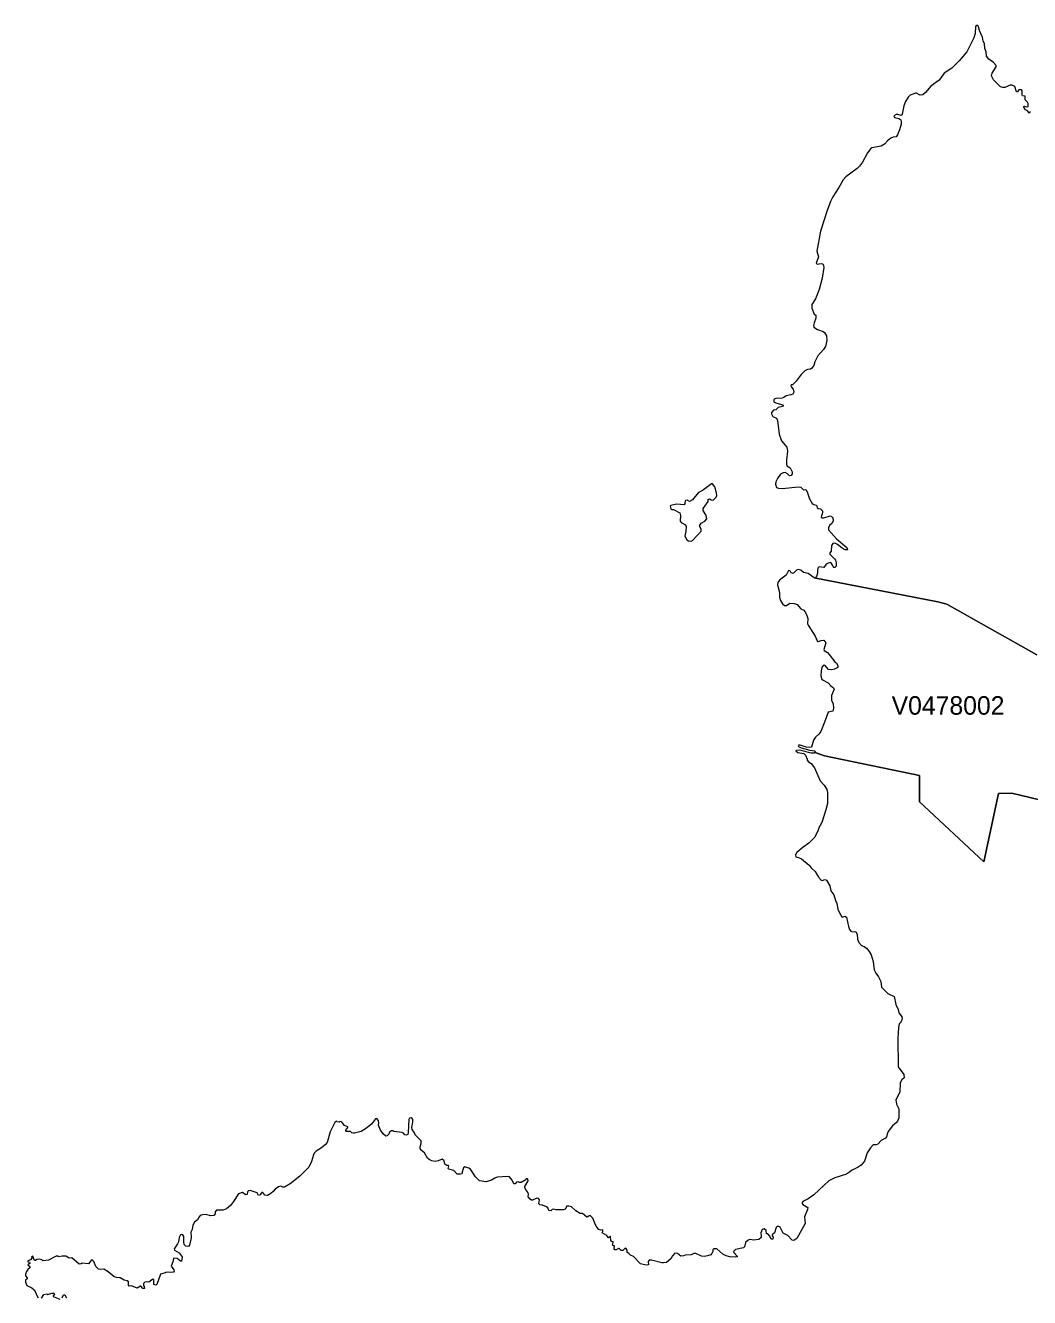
# Model space of a CAD drawing. Extents: x 369010 to 735936, y 6377141 to 6616555.
# Drawn here: x 445777 to 451203, y 6497979 to 6504854 of the extents above; entities that cross this region are included whole.
import ezdxf
from ezdxf.enums import TextEntityAlignment as Align

# ---------------------------------------------------------------- set-up
doc = ezdxf.new("R2010")
doc.units = 0
doc.header["$LTSCALE"] = 40
doc.layers.add('3', color=7, linetype='Continuous', lineweight=13)
doc.layers.add('4', color=7, linetype='Continuous')

msp = doc.modelspace()

# ---------------------------------------------------------------- linework, layer by layer
at = {"layer": '3'}
for points in [[(451162.75, 6504500.78), (451159.61, 6504506.24), (451152.82, 6504508.06), (451144.21, 6504505.58), (451137.92, 6504495.65), (451132.46, 6504496.31), (451123.69, 6504524.45), (451108.8, 6504531.24), (451097.87, 6504532.06), (451069.57, 6504519.48), (451058.65, 6504518.82), (451045.74, 6504521.97), (451007.84, 6504560.53), (450997.41, 6504581.38), (451001.22, 6504596.11), (451022.9, 6504630.7), (451022.24, 6504637.16), (451007.51, 6504655.03), (450982.02, 6504672.91), (450970.1, 6504688.96), (450967.95, 6504711.3), (450960.83, 6504730.5), (450959.51, 6504756.82), (450952.23, 6504769.56), (450948.09, 6504791.74), (450944.45, 6504798.03), (450931.54, 6504827.82), (450926.91, 6504846.52), (450922.44, 6504854.46), (450918.63, 6504854.46), (450909.86, 6504848.01), (450908.7, 6504810.61), (450902.08, 6504786.77), (450863.19, 6504712.63), (450823.14, 6504662.48), (450782.26, 6504624.25), (450741.87, 6504596.77), (450714.73, 6504559.37), (450668.89, 6504525.44), (450640.09, 6504492.18), (450625.69, 6504479.6), (450611.62, 6504477.78), (450592.09, 6504489.2), (450586.3, 6504489.2), (450557.5, 6504477.78), (450546.58, 6504466.85), (450531.52, 6504443.85), (450523.24, 6504420.68), (450513.97, 6504375.33), (450509.17, 6504366.89), (450491.63, 6504373.01), (450482.69, 6504372.35), (450469.78, 6504366.06), (450473.59, 6504357.29), (450496.1, 6504351.66), (450507.52, 6504344.55), (450509.51, 6504334.29), (450508.18, 6504320.22), (450499.91, 6504289.76), (450489.64, 6504263.95), (450482.69, 6504253.35), (450465.32, 6504251.04), (450452.57, 6504244.75), (450435.86, 6504231.18), (450419.8, 6504213.63), (450400.6, 6504201.55), (450350.46, 6504192.12), (450344.99, 6504189.3), (450326.46, 6504165.97), (450300.47, 6504115.99), (450284.09, 6504093.64), (450271.35, 6504081.4), (450209.61, 6504036.05), (450195.21, 6504019.99), (450172.7, 6503978.29), (450139.77, 6503928.47), (450126.69, 6503903.48), (450108.49, 6503853.5), (450073.24, 6503742.11), (450054.04, 6503633.87), (450061.65, 6503603.25), (450049.57, 6503568.99), (450055.86, 6503564.03), (450076.71, 6503568), (450085.32, 6503565.19), (450090.12, 6503557.74), (450091.11, 6503546.32), (450081.18, 6503488.06), (450066.45, 6503426.5), (450045.76, 6503376.68), (450026.56, 6503345.9), (450026.73, 6503326.7), (450038.48, 6503293.43), (450047.09, 6503287.97), (450048.41, 6503272.91), (450038.48, 6503247.75), (450035.17, 6503232.69), (450037.82, 6503224.58), (450057.02, 6503211.18), (450087.64, 6503200.58)], [(451204.79, 6504388.74), (451202.14, 6504380.96), (451189.06, 6504394.2), (451181.12, 6504398.34), (451172.02, 6504412.73), (451172.02, 6504416.87), (451176.32, 6504417.53), (451185.59, 6504414.06), (451194.86, 6504417.2), (451195.85, 6504432.93), (451192.21, 6504439.88), (451179.8, 6504451.79), (451178.8, 6504471.98), (451164.74, 6504473.81), (451162.42, 6504477.45), (451162.75, 6504500.78)], [(450087.64, 6503200.58), (450095.25, 6503194.13), (450105.84, 6503177.74), (450107.83, 6503152.59), (450099.55, 6503118.82), (450089.46, 6503103.1), (450058.01, 6503069.67), (450041.96, 6503036.24), (450036.49, 6503017.37), (450026.56, 6503001.98), (450019.45, 6502997.68), (450002.73, 6502994.2), (449988, 6502987.41), (449969.3, 6502968.22), (449942.32, 6502931.14), (449921.14, 6502911.94), (449914.35, 6502912.61), (449912.2, 6502908.3), (449913.69, 6502902.18), (449924.61, 6502888.11), (449929.74, 6502872.06), (449924.28, 6502862.46), (449912.7, 6502857.99), (449887.71, 6502852.69), (449874.14, 6502843.09), (449865.86, 6502840.61), (449832.43, 6502838.29), (449822.83, 6502834.16), (449820.18, 6502829.03), (449820.18, 6502822.9), (449822.83, 6502819.26), (449836.24, 6502812.97), (449868.67, 6502803.54), (449871.65, 6502800.06), (449867.52, 6502794.93), (449844.68, 6502789.47), (449832.43, 6502777.89), (449818.2, 6502774.74), (449808.6, 6502762.49), (449808.93, 6502755.38), (449815.05, 6502741.81), (449834.41, 6502731.54), (449839.88, 6502719.96), (449850.14, 6502644.82), (449862.55, 6502609.4), (449891.51, 6502574.48), (449894.16, 6502554.12), (449888.7, 6502507.29), (449888.7, 6502482.79), (449891.84, 6502475.18), (449908.89, 6502463.59), (449920.48, 6502441.42), (449920.48, 6502430.82), (449913.69, 6502421.72), (449908.23, 6502419.57), (449903.1, 6502421.39), (449895.49, 6502431.15), (449881.91, 6502438.11), (449870.99, 6502435.95), (449856.26, 6502429.17), (449839.88, 6502406.66), (449832.1, 6502388.29), (449830.77, 6502375.55), (449835.9, 6502358.17), (449845.34, 6502353.7), (449868.34, 6502351.38), (449953.25, 6502361.31), (449966.82, 6502359.16), (449980.89, 6502344.6), (449994.13, 6502345.92), (450000.91, 6502334.34), (450013.66, 6502295.77), (450028.22, 6502270.45), (450037.49, 6502265.32), (450051.89, 6502261.02), (450055.86, 6502247.61), (450060, 6502243.64), (450073.4, 6502242.81), (450083.83, 6502231.89), (450084.33, 6502219.97), (450077.71, 6502204.75), (450077.04, 6502196.47), (450081.18, 6502192.66), (450091.44, 6502192.66), (450124.87, 6502203.26), (450137.45, 6502196.47), (450142.25, 6502183.56), (450142.25, 6502175.95), (450135.14, 6502163.04), (450122.06, 6502152.45), (450115.94, 6502139.54), (450117.1, 6502127.62), (450159.63, 6502079.46), (450215.57, 6502032.95), (450219.38, 6502022.86), (450217.06, 6502020.37), (450207.13, 6502020.04), (450190.08, 6502029.97), (450165.42, 6502049.5), (450150.86, 6502055.63)], [(450150.86, 6502055.63), (450139.93, 6502054.14), (450132.65, 6502043.88), (450130.67, 6502012.93), (450123.22, 6502004.98), (450123.22, 6501996.54), (450148.71, 6501972.38), (450153.84, 6501964.76), (450158.31, 6501949.37), (450157.64, 6501932.33), (450151.19, 6501924.88), (450144.9, 6501925.21), (450140.93, 6501928.35), (450136.46, 6501941.26), (450128.35, 6501951.52), (450113.95, 6501949.04), (450103.36, 6501943.25), (450091.44, 6501924.55), (450066.45, 6501927.69), (450058.34, 6501921.07), (450056.19, 6501909.49), (450056.36, 6501893.43), (450052.22, 6501876.72), (450044.94, 6501867.94), (450038.81, 6501868.61)], [(451242.85, 6501453.52), (450756.27, 6501726.94), (450707.28, 6501740.01), (450038.98, 6501868.61), (450038.81, 6501868.61), (450038.81, 6501868.61), (450007.2, 6501892.77), (449981.55, 6501898.23), (449966.16, 6501909.82), (449951.92, 6501913.95), (449943.32, 6501911.31), (449925.28, 6501893.1), (449914.35, 6501896.58), (449911.54, 6501904.02), (449906.91, 6501907.5), (449900.95, 6501907.83), (449888.04, 6501883.67), (449851.13, 6501856.03), (449841.7, 6501843.95), (449840.21, 6501831.04), (449851.46, 6501789.33), (449851.46, 6501764.17), (449856.76, 6501747.46), (449867.85, 6501728.26), (449878.77, 6501718.83), (449889.69, 6501718.83), (449908.23, 6501733.06), (449931.4, 6501729.75), (449946.46, 6501724.62), (449967.15, 6501700.79), (449982.54, 6501693.83), (449989, 6501687.71), (449997.93, 6501671), (450003.73, 6501649.48), (450003.06, 6501620.85), (450006.21, 6501612.41), (450045.1, 6501554.65), (450055.53, 6501528.66), (450061.32, 6501525.35), (450076.71, 6501530.48), (450090.78, 6501531.81), (450102.37, 6501517.74), (450091.77, 6501481.99), (450093.76, 6501475.53), (450111.63, 6501464.94), (450120.74, 6501455.01), (450150.03, 6501414.79), (450158.97, 6501407.68), (450167.24, 6501394.93), (450166.75, 6501384.67), (450148.71, 6501375.24), (450131.99, 6501371.43), (450116.6, 6501373.75), (450096.9, 6501396.26), (450086.97, 6501395.27), (450080.85, 6501383.68), (450076.38, 6501366.96), (450075.39, 6501341.81), (450078.86, 6501323.93), (450087.3, 6501316.82), (450114.94, 6501300.76), (450128.68, 6501285.7), (450143.91, 6501274.12), (450147.38, 6501267.33), (450131.99, 6501233.9), (450131.66, 6501205.93), (450142.25, 6501189.54), (450143.91, 6501164.39), (450139.27, 6501149.33), (450113.95, 6501142.21), (450095.25, 6501089.25), (450074.4, 6501039.1), (450064.47, 6501023.71), (450046.76, 6501007.32), (450035.17, 6500991.6), (450028.72, 6500965.78), (450023.92, 6500954.53)], [(450038.81, 6501868.61), (450707.28, 6501740.01), (450756.27, 6501726.94), (451242.85, 6501453.52)], [(451301.77, 6500658.28), (451106.15, 6500705.44), (451034.65, 6500702.8), (450956.04, 6500334.05), (450608.64, 6500658.11), (450608.48, 6500800.78), (450094.59, 6500907.36), (450044.27, 6500925.07), (450039.47, 6500921.76), (450022.76, 6500921.76), (449959.37, 6500938.14), (449941.66, 6500936.32), (449939.51, 6500934.34), (449950.76, 6500924.41), (449982.21, 6500920.1), (449991.48, 6500909.84), (450000.25, 6500889.65), (450000.25, 6500882.87), (450007.53, 6500874.92), (450022.43, 6500865.16), (450040.96, 6500842.48), (450070.92, 6500771.32), (450092.44, 6500749.14), (450108.16, 6500724.81), (450111.14, 6500708.09), (450110.14, 6500649.5), (450102.7, 6500616.07), (450079.86, 6500546.73), (450061.65, 6500513.96), (450060, 6500506.18), (450041.63, 6500467.62), (450010.51, 6500435.84), (449979.23, 6500413.33), (449945.8, 6500385.36), (449938.19, 6500372.78), (449940.34, 6500360.7), (449954.57, 6500357.39), (449971.29, 6500349.78), (450011.83, 6500315.68), (450022.76, 6500301.12), (450043.61, 6500281.59), (450062.15, 6500250.97), (450076.05, 6500234.59), (450081.18, 6500233.43), (450096.9, 6500237.9), (450106.01, 6500234.59), (450123.55, 6500204.46), (450129.01, 6500178.31), (450145.4, 6500155.31), (450154.5, 6500124.36), (450161.28, 6500108.97), (450166.91, 6500078.18), (450173.04, 6500062.63), (450187.93, 6500036.64), (450192.73, 6500035.32), (450203.98, 6500040.12), (450213.92, 6500034.99), (450224.84, 6499984.84), (450230.47, 6499967.79), (450236.59, 6499960.35), (450246.19, 6499955.88), (450259.26, 6499958.53), (450264.06, 6499955.71), (450271.51, 6499943.13), (450273, 6499916.16), (450279.45, 6499898.12), (450294.02, 6499881.73), (450309.08, 6499876.6), (450321.66, 6499867.33), (450335.73, 6499849.95), (450345.99, 6499831.91), (450357.9, 6499796), (450363.37, 6499750.98), (450371.48, 6499731.95), (450385.87, 6499713.58), (450398.78, 6499686.6), (450401.93, 6499657.47), (450436.35, 6499622.06), (450471.6, 6499606.66), (450480.71, 6499563.8), (450492.29, 6499536.82), (450495.77, 6499518.95), (450515.13, 6499495.11), (450513.15, 6499494.45)], [(450023.92, 6500954.53), (450016.3, 6500952.05), (449996.28, 6500953.87), (449962.85, 6500965.45), (449953.91, 6500964.46), (449952.25, 6500960.65), (449953.91, 6500957.51), (449968.64, 6500950.72), (450014.98, 6500936.82), (450040.96, 6500933.34), (450043.94, 6500930.2), (450044.27, 6500925.07)], [(450044.27, 6500925.07), (450094.59, 6500907.36), (450608.48, 6500800.78), (450608.64, 6500658.11), (450956.04, 6500334.05), (451034.65, 6500702.8), (451106.15, 6500705.44), (451301.77, 6500658.28)], [(450513.15, 6499494.45), (450514.14, 6499488.66), (450510.83, 6499474.92), (450504.21, 6499462.34), (450498.75, 6499457.88), (450494.78, 6499438.51), (450491.63, 6499381.25), (450493.29, 6499227), (450522.75, 6499184.63), (450524.73, 6499166.59), (450511.82, 6499155.67), (450503.22, 6499140.6), (450502.55, 6499090.13), (450481.04, 6499048.09), (450483.85, 6499025.25), (450495.77, 6498999.43), (450495.77, 6498950.61), (450489.31, 6498932.4), (450483.85, 6498924.62), (450463, 6498906.91), (450438.17, 6498876.79), (450434.37, 6498867.69), (450430.23, 6498847.17), (450425.1, 6498840.71), (450400.93, 6498828.79), (450382.73, 6498808.27), (450373.63, 6498805.13), (450358.23, 6498804.47), (450342.51, 6498789.24), (450325.13, 6498762.26), (450310.9, 6498715.76), (450293.03, 6498694.24), (450277.47, 6498683.81), (450244.37, 6498667.43), (450212.92, 6498646.91), (450150.03, 6498626.05), (450117.76, 6498609.34), (450037.49, 6498534.36), (450006.87, 6498512.52), (449977.74, 6498497.79), (449974.43, 6498492.66), (449974.43, 6498488.52), (449978.07, 6498483.06), (450004.72, 6498466.67), (450002.73, 6498454.42), (449986.68, 6498415.53), (449989.66, 6498380.44), (449944.31, 6498297.86), (449928.26, 6498287.6), (449920.48, 6498289.91), (449895.98, 6498314.91), (449871.65, 6498327.81), (449854.61, 6498360.58), (449848.48, 6498363.73), (449838.55, 6498363.73), (449833.09, 6498358.6), (449824.65, 6498328.81), (449812.73, 6498317.55), (449812.73, 6498313.58), (449817.37, 6498305.31), (449815.05, 6498295.04), (449806.78, 6498295.04), (449798.67, 6498310.44), (449788.74, 6498323.35), (449781.29, 6498324.17), (449779.3, 6498342.21), (449768.05, 6498349.99), (449757.46, 6498346.35), (449750.84, 6498328.48), (449753.32, 6498310.44), (449751.66, 6498303.98), (449739.58, 6498293.39), (449711.61, 6498288.92), (449691.25, 6498293.06), (449682.32, 6498289.58), (449668.58, 6498276.34), (449662.79, 6498254.17), (449657.49, 6498248.7), (449614.13, 6498239.44), (449603.54, 6498228.51), (449603.87, 6498223.71), (449623.23, 6498203.36), (449622.57, 6498199.55), (449611.32, 6498196.9), (449582.35, 6498198.89), (449563.15, 6498204.68), (449544.45, 6498213.95), (449513.34, 6498241.92), (449498.44, 6498243.24), (449490.83, 6498236.79), (449491.16, 6498228.18), (449486.53, 6498216.6), (449480.24, 6498211.13), (449462.86, 6498204.35), (449444.16, 6498201.53), (449429.1, 6498202.36), (449399.8, 6498217.59), (449388.55, 6498216.93), (449374.81, 6498209.81), (449342.04, 6498209.15)], [(448392.21, 6498631.35), (448382.78, 6498634), (448326.01, 6498630.02), (448312.44, 6498625.23), (448294.9, 6498614.63), (448265.93, 6498605.53), (448230.02, 6498610.66), (448209, 6498632.01), (448181.86, 6498672.39), (448172.09, 6498678.85), (448150.91, 6498685.97), (448143.13, 6498680.5), (448135.35, 6498652.04), (448136.01, 6498648.89), (448127.9, 6498645.91), (448108.87, 6498646.24), (448091.99, 6498666.6), (448063.85, 6498673.72), (448061.37, 6498676.86), (448064.85, 6498690.76), (448061.7, 6498693.08), (448053.26, 6498693.08), (448043, 6498700.53), (448039.36, 6498717.58), (448029.1, 6498727.67), (448006.09, 6498717.58), (447992.52, 6498714.43), (447973.16, 6498718.9), (447958.59, 6498725.02), (447948.66, 6498733.13), (447933.77, 6498761.27), (447917.22, 6498774.51), (447909.11, 6498784.27), (447909.11, 6498793.54), (447915.56, 6498811.09), (447914.9, 6498825.48), (447883.29, 6498858.59), (447878.82, 6498870.17), (447866.24, 6498887.88), (447864.92, 6498898.97), (447869.72, 6498927.27), (447869.72, 6498941.83), (447866.57, 6498946.8), (447860.45, 6498950.61), (447852.34, 6498948.29), (447848.37, 6498942.17), (447844.89, 6498871.16), (447842.24, 6498861.4), (447833.31, 6498857.59), (447826.52, 6498858.59), (447819.4, 6498867.52), (447812.95, 6498871.5), (447767.6, 6498877.29), (447761.48, 6498881.09), (447755.35, 6498881.09), (447743.44, 6498872.65), (447740.46, 6498862.06), (447732.02, 6498852.96), (447724.74, 6498852.13), (447709.51, 6498863.72), (447694.94, 6498884.74), (447684.35, 6498910.55), (447685.51, 6498923.46), (447684.02, 6498934.39), (447678.06, 6498945.48), (447671.61, 6498946.47), (447667.8, 6498944.48), (447646.45, 6498917.01), (447614.51, 6498891.52), (447591.17, 6498876.63), (447555.59, 6498867.19), (447547.98, 6498867.19), (447539.87, 6498870.17), (447532.75, 6498876.63), (447509.41, 6498875.96), (447507.26, 6498879.44), (447507.92, 6498884.4), (447518.85, 6498897.98), (447518.52, 6498902.44), (447500.48, 6498908.9), (447488.73, 6498925.45), (447482.6, 6498930.58), (447473.33, 6498929.59), (447471.68, 6498927.27), (447460.09, 6498929.92), (447457.45, 6498932.23), (447449.01, 6498925.45), (447423.19, 6498875.63), (447406.47, 6498818.04), (447397.37, 6498807.44), (447376.35, 6498789.41), (447347.55, 6498770.04), (447337.62, 6498759.28), (447333.32, 6498751.5), (447321.73, 6498714.1), (447308.16, 6498683.32), (447259.67, 6498634.66), (447206.71, 6498593.61), (447177.25, 6498575.74), (447167.98, 6498575.74)], [(449342.04, 6498209.15), (449332.28, 6498205.01), (449318.54, 6498202.69), (449299.51, 6498218.25), (449286.43, 6498218.42), (449273.19, 6498205.67), (449264.42, 6498188.29), (449240.09, 6498168.93), (449224.37, 6498166.45), (449215.26, 6498167.11), (449160.65, 6498181.51), (449147.9, 6498181.51), (449141.78, 6498175.05), (449143.93, 6498156.52), (449130.53, 6498154.86), (449100.57, 6498160.99), (449062.01, 6498202.03), (449046.95, 6498208.82), (449036.85, 6498216.76), (449027.75, 6498222.06), (449027.42, 6498234.97), (449022.62, 6498244.23), (449017.16, 6498245.89), (449004.91, 6498233.31), (448995.47, 6498234.3), (448984.22, 6498244.9), (448981.24, 6498244.9), (448968.66, 6498236.79), (448960.88, 6498237.45), (448957.91, 6498243.24), (448960.22, 6498258.14), (448954.76, 6498258.47), (448948.97, 6498261.78), (448953.11, 6498276.34), (448951.78, 6498281.8), (448943.84, 6498279.82), (448941.19, 6498284.62), (448942.84, 6498286.6), (448940.86, 6498287.27), (448937.55, 6498308.62), (448935.07, 6498309.28), (448927.29, 6498302.49), (448924.97, 6498303.15), (448917.52, 6498314.74), (448893.36, 6498328.97), (448896.67, 6498336.75), (448896.01, 6498343.21), (448892.37, 6498344.7), (448884.26, 6498342.88), (448875.32, 6498346.68), (448864.89, 6498358.93), (448856.78, 6498372.83), (448843.54, 6498407.75), (448827.82, 6498423.64), (448822.19, 6498421.32), (448815.74, 6498414.87), (448810.61, 6498414.54), (448786.11, 6498432.91), (448774.2, 6498433.57), (448750.53, 6498447.47), (448727.85, 6498469.15), (448713.79, 6498472.46), (448702.37, 6498472.46), (448692.44, 6498457.57), (448685.98, 6498453.93), (448643.28, 6498453.27), (448629.05, 6498456.58), (448623.59, 6498454.59), (448616.47, 6498448.14), (448604.89, 6498450.45), (448599.26, 6498463.69), (448592.14, 6498469.49), (448570.96, 6498478.92), (448556.06, 6498479.75), (448551.26, 6498485.37), (448554.08, 6498508.21), (448549.61, 6498515), (448539.84, 6498515.66), (448517, 6498506.56), (448511.38, 6498506.56), (448504.26, 6498511.85), (448494, 6498524.1), (448495.98, 6498537.67), (448493.34, 6498545.12), (448483.07, 6498559.02), (448475.96, 6498572.93), (448474.96, 6498579.71), (448492.67, 6498610), (448491.68, 6498619.1), (448489.86, 6498621.09), (448483.07, 6498620.76), (448477.12, 6498613.97), (448455.6, 6498600.73), (448447.16, 6498601.06), (448438.39, 6498605.53), (448430.28, 6498602.22), (448422.5, 6498593.28), (448415.88, 6498593.94), (448407.11, 6498613.64), (448392.21, 6498631.35)], [(447167.98, 6498575.74), (447156.23, 6498580.7), (447144.64, 6498578.06), (447126.6, 6498564.82), (447115.35, 6498552.24), (447101.94, 6498541.48), (447083.9, 6498531.22), (447070.99, 6498532.54), (447059.08, 6498547.11), (447054.77, 6498547.27), (447049.98, 6498543.47), (447045.18, 6498534.36), (447036.4, 6498530.23), (447028.29, 6498544.46), (446990.23, 6498557.37), (446981.79, 6498556.04), (446976, 6498551.58), (446975.66, 6498536.68), (446967.89, 6498535.03), (446946.87, 6498547.93), (446927.34, 6498539.99), (446901.68, 6498498.28), (446884.64, 6498477.26), (446862.96, 6498458.56), (446845.41, 6498451.45), (446809.33, 6498451.45), (446801.55, 6498442.67), (446801.88, 6498431.75), (446795.1, 6498423.64), (446776.89, 6498420.99), (446753.06, 6498429.1), (446733.7, 6498426.79), (446720.46, 6498422.32), (446714.66, 6498415.53), (446706.89, 6498399.31), (446690.67, 6498386.4), (446681.07, 6498371.01), (446677.76, 6498346.35), (446670.64, 6498332.12), (446671.63, 6498303.15), (446669.32, 6498285.61), (446662.53, 6498261.78), (446657.07, 6498255.65), (446643.83, 6498256.48), (446634.73, 6498266.91), (446632.57, 6498279.82), (446632.24, 6498308.95), (446627.94, 6498317.88), (446620, 6498320.2), (446614.7, 6498318.88), (446607.09, 6498303.65), (446603.11, 6498280.48), (446598.98, 6498268.89), (446580.27, 6498242.41), (446582.43, 6498234.64), (446606.42, 6498221.06), (446623.47, 6498199.38), (446619.33, 6498176.38), (446614.7, 6498176.05), (446597.32, 6498189.95), (446578.29, 6498192.93), (446576.3, 6498190.94), (446573.65, 6498172.57), (446564.39, 6498149.24), (446578.95, 6498128.55), (446579.61, 6498121.43), (446577.3, 6498117.29), (446563.06, 6498114.31), (446539.89, 6498116.96), (446526.32, 6498110.84), (446505.63, 6498105.71), (446487.1, 6498050.43), (446480.31, 6498046.79), (446470.38, 6498050.1), (446469.72, 6498075.59), (446464.92, 6498077.9), (446442.91, 6498063.34), (446429.67, 6498064.66), (446421.56, 6498061.68), (446413.78, 6498055.23), (446415.43, 6498044.64), (446418.58, 6498038.84), (446419.57, 6498029.08), (446410.8, 6498027.76), (446400.87, 6498041), (446397.56, 6498041), (446380.51, 6498029.41), (446349.89, 6498042.32), (446336.82, 6498041.33), (446333.34, 6498046.46), (446333.34, 6498064.99), (446326.89, 6498069.13), (446309.68, 6498072.94), (446288.49, 6498086.34), (446268.47, 6498087.5), (446255.39, 6498092.14), (446223.12, 6498118.62), (446199.95, 6498132.19), (446183.07, 6498130.53), (446170.82, 6498132.85)], [(446170.82, 6498132.85), (446157.25, 6498147.91), (446146.65, 6498173.56), (446136.89, 6498182.83), (446131.1, 6498181.51), (446125.3, 6498169.92), (446117.86, 6498161.48), (446082.94, 6498164.46), (446077.8, 6498161.48), (446067.38, 6498160.66), (446027.66, 6498193.26), (446012.76, 6498192.93), (445994.06, 6498202.53), (445975.69, 6498203.19), (445955, 6498199.71), (445953.68, 6498202.86), (445942.09, 6498202.2), (445900.72, 6498181.34), (445870.92, 6498177.37), (445864.47, 6498182.5), (445850.9, 6498187.47), (445837.66, 6498185.81), (445830.05, 6498179.36), (445825.41, 6498179.85), (445815.98, 6498202.86), (445809.85, 6498199.71), (445810.52, 6498192.27), (445804.06, 6498183.83), (445788.83, 6498177.7), (445788.83, 6498173.23), (445797.61, 6498170.59), (445800.25, 6498167.44), (445799.92, 6498164.13), (445790.49, 6498158.01), (445789.83, 6498155.69), (445800.92, 6498147.08), (445800.59, 6498139.64), (445790.16, 6498130.53), (445781.72, 6498119.61), (445776.59, 6498105.05), (445777.58, 6498096.27), (445785.36, 6498085.35), (445785.03, 6498081.05), (445776.59, 6498072.44), (445777.58, 6498063.34), (445783.7, 6498045.3), (445811.84, 6498032.39), (445823.43, 6498021.3), (445831.53, 6498009.05), (445837.66, 6497989.69), (445844.78, 6497977.44)], [(445863.15, 6497976.78), (445875.56, 6497996.14), (445891.61, 6497998.96), (445896.74, 6497996.48), (445920.08, 6498003.92), (445929.84, 6498003.26), (445932.66, 6498001.28), (445932.99, 6497996.81), (445925.87, 6497988.7), (445926.53, 6497985.72), (445961.79, 6497969.99)], [(445974.36, 6497978.1), (445982.47, 6497994.49), (445988.93, 6497994.49), (445998.53, 6497977.77)]]:
    msp.add_lwpolyline(points, dxfattribs=at)
msp.add_lwpolyline([(449484.04, 6502376.21), (449440.02, 6502344.27), (449412.05, 6502328.87), (449382.09, 6502290.97), (449366.04, 6502281.04), (449352.8, 6502288.66), (449344.19, 6502287.66), (449341.05, 6502283.53), (449338.73, 6502263.33), (449295.7, 6502267.47), (449264.25, 6502260.35), (449261.27, 6502256.22), (449263.59, 6502242.81), (449269.88, 6502238.84), (449278.98, 6502239.17), (449313.08, 6502219.97), (449316.22, 6502206.4), (449315.56, 6502175.29), (449320.36, 6502168.17), (449343.86, 6502154.93), (449347.17, 6502147.32), (449345.52, 6502121.66), (449339.06, 6502093.69), (449350.98, 6502074), (449359.25, 6502068.54), (449373.82, 6502066.55), (449381.43, 6502071.51), (449428.43, 6502120.67), (449427.77, 6502131.92), (449421.32, 6502144.67), (449420.32, 6502154.1), (449427.44, 6502164.03), (449447.96, 6502175.29), (449458.06, 6502187.2), (449455.74, 6502205.08), (449439.03, 6502233.05), (449438.36, 6502243.97), (449466.66, 6502282.04), (449466, 6502293.29), (449473.78, 6502296.77), (449482.39, 6502289.98), (449492.32, 6502289.65), (449509.36, 6502304.38), (449512.34, 6502313.81), (449511.02, 6502329.2), (449502.91, 6502359.99), (449490.17, 6502376.37)], close=True, dxfattribs=at)

# ---------------------------------------------------------------- texts
at = {"layer": '4'}
msp.add_text('V0478002', height=100, dxfattribs=at).set_placement((450762.25, 6501129.4), align=Align.CENTER)

doc.saveas('drawing.dxf')
